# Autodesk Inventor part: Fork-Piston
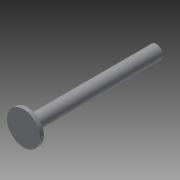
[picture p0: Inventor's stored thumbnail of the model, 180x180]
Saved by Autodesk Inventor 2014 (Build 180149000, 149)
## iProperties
Shininess: 64.0
Length Units: 11272
Angle Units: 11279
Time Units: 11290
Mass Units: 11286
Length Display Precision: 3
Angle Display Precision: 2
Compacted: True
Created: 2001-11
Part Number: Fork-Piston
Document SubType Name: Modeling
Designer: Autodesk, Inc.
Mass: 6.28409 g
Surface Area: 33.2778 cm^2
Volume: 6.28409 cm^3
Density: 1 g/cm^3
Material: Generic
Appearance: Default
Density: 0.0
Volumn: 0.0
Area: 0.0
PropertySet Name: Model Information
Control State: 0
Master: False
Checked Out: False
Author: Autodesk, Inc.
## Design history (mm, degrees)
sketch "Sketch1"
  geometry: C1 r 10.985 at (6.128, 0) reference
extrude "Extrusion1" new body sketch "Sketch1" distance "d0" = 2.54; taper "d1" = 0 deg
sketch "Sketch2"
  geometry: C1 r 4.445 at (0, 0) reference
extrude "Extrusion2" join sketch "Sketch2" distance "d2" = 85.725; taper "d3" = 0 deg
body "Solid1"
node "Reference1"
node "Reference2"
